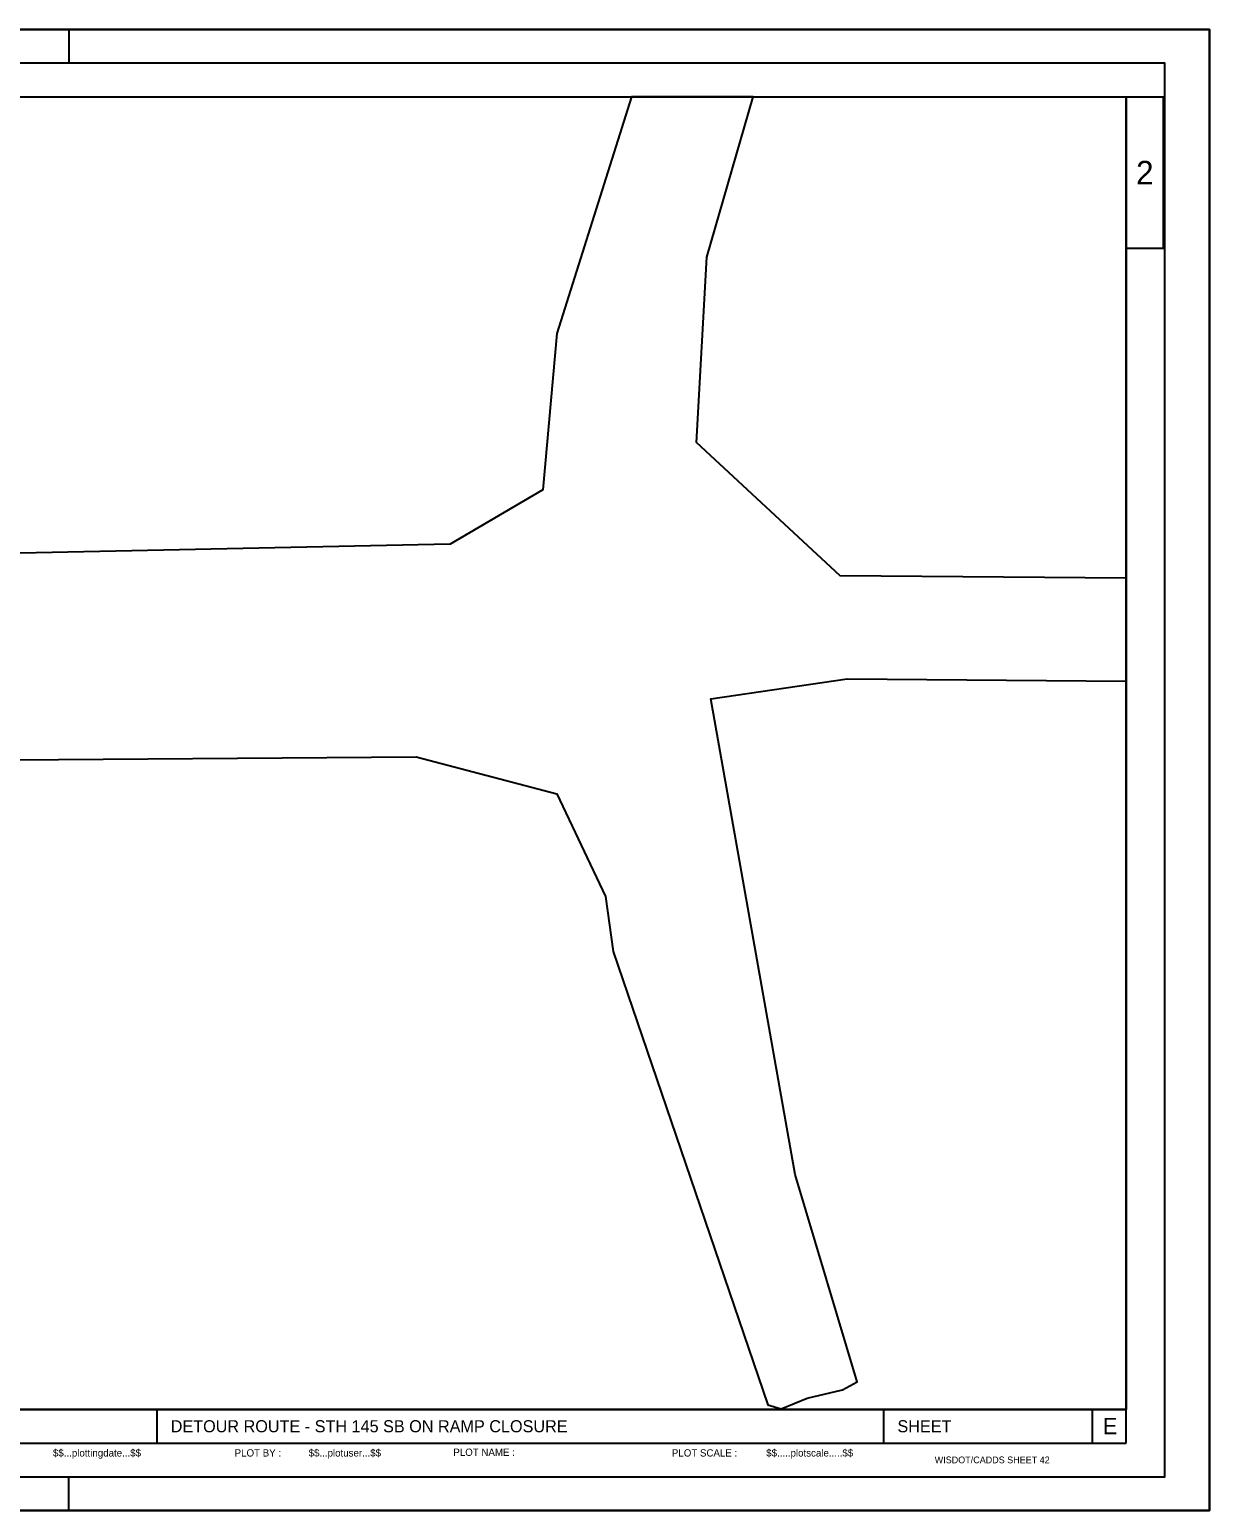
# Model space of a CAD drawing. Extents: x 359903 to 361603, y 132699 to 133799.
# Drawn here: x 360726 to 361603, y 132699 to 133799 of the extents above; entities that cross this region are included whole.
import ezdxf

# ---------------------------------------------------------------- set-up
doc = ezdxf.new("R2010")
doc.units = 0
for name, color, linetype in [('Default', 7, 'Continuous'), ('P_Kapur_PFFE CELL [KAPUR_CADDS_LEVELS]', 7, 'Continuous'), ('P_RDWY_Text', 7, 'Continuous'), ('PLT_Sheet_Border', 7, 'Continuous'), ('PLT_Sheet_Info', 7, 'Continuous')]:
    doc.layers.add(name, color=color, linetype=linetype)

msp = doc.modelspace()

# ---------------------------------------------------------------- linework, layer by layer
at = {"layer": 'Default'}
msp.add_lwpolyline([(361541.3, 132774.3), (360298.3, 132774.3), (359966.3, 133404.1), (359966.3, 133749.3), (361541.3, 133749.3)], close=True, dxfattribs=at)
for points in [[(360408.4, 133749.3), (361541.3, 133749.3), (361541.3, 132774.3), (360298.3, 132774.3)], [(360681.2, 133256.7), (361013.7, 133259.1), (361118.3, 133231.7), (361154.3, 133155.2), (361160.1, 133114.5), (361275, 132777.6), (361284.9, 132774.8), (361304.2, 132782.7), (361330.5, 132788.9), (361341.3, 132794.7), (361295.2, 132948.7), (361232.7, 133302.2), (361333.9, 133317), (361541.3, 133315.4), (361541.3, 133391.9), (361328.7, 133393.6), (361221.9, 133492.6), (361229.7, 133630.3), (361264.2, 133749.3), (361173.7, 133749.3), (361118.3, 133573.6), (361107.7, 133457.4), (361039, 133417.1), (360671.8, 133409.4)]]:
    msp.add_lwpolyline(points, dxfattribs=at)
at = {"layer": 'P_Kapur_PFFE CELL [KAPUR_CADDS_LEVELS]'}
msp.add_lwpolyline([(359903.1, 133799.3), (361603.1, 133799.3), (361603.1, 132699.3), (359903.1, 132699.3), (359903.1, 133799.3)], dxfattribs=at)
at = {"layer": 'P_RDWY_Text'}
msp.add_lwpolyline([(359903.1, 133799.3), (361603.1, 133799.3), (361603.1, 132699.3), (359903.1, 132699.3)], close=True, dxfattribs=at)
at = {"layer": 'PLT_Sheet_Border'}
for points in [[(359903.1, 132699.3), (361603.1, 132699.3), (361603.1, 133799.3), (359903.1, 133799.3)], [(359915.1, 132724.3), (361570.1, 132724.3), (361570.1, 133774.3), (359915.1, 133774.3)]]:
    msp.add_lwpolyline(points, close=True, dxfattribs=at)
at = {"layer": 'PLT_Sheet_Info'}
for p, q in [((360730.6, 133799.3), (360780.6, 133799.3)), ((360755.6, 133799.3), (360755.6, 133774.3)), ((361553.1, 133799.3), (361603.1, 133799.3)), ((361603.1, 133749.3), (361603.1, 133799.3)), ((359966.3, 133749.3), (361541.3, 133749.3)), ((361541.3, 132749.3), (361541.3, 133749.3)), ((359966.3, 132774.3), (361541.3, 132774.3)), ((360821.3, 132749.3), (360821.3, 132774.3)), ((361361.3, 132749.3), (361361.3, 132774.3)), ((361516.3, 132749.3), (361516.3, 132774.3)), ((359966.3, 132749.3), (361541.3, 132749.3)), ((361603.1, 132699.3), (361603.1, 132749.3)), ((360755.6, 132699.3), (360755.6, 132724.3)), ((360730.6, 132699.3), (360780.6, 132699.3)), ((361553.1, 132699.3), (361603.1, 132699.3))]:
    msp.add_line(p, q, dxfattribs=at)
msp.add_lwpolyline([(361541.3, 133749.3), (361568.8, 133749.3), (361568.8, 133636.8), (361541.3, 133636.8)], close=True, dxfattribs=at)

# ---------------------------------------------------------------- texts
for s, height, p in [('2', 17.5, (361548.6, 133684.3)), ('DETOUR ROUTE - STH 145 SB ON RAMP CLOSURE', 9, (360831.3, 132757.3)), ('SHEET ', 9, (361371.3, 132757.3)), ('E', 12, (361523.9, 132755.9)), ('PLOT NAME :                      ', 5.4, (361041.3, 132739.8)), ('PLOT SCALE : ', 5.4, (361203.7, 132739.3)), ('$$.....plotscale.....$$', 5.4, (361273.8, 132739.3)), ('WISDOT/CADDS SHEET 42', 5, (361399, 132734.3))]:
    msp.add_text(s, height=height, dxfattribs=at).set_placement(p)
for s, p in [('$$...plottingdate...$$', (360743.8, 132739.3)), ('PLOT BY :', (360878.8, 132739.3)), ('$$...plotuser...$$', (360933.8, 132739.3))]:
    msp.add_text(s, height=5.4, rotation=360, dxfattribs=at).set_placement(p)

doc.saveas('drawing.dxf')
